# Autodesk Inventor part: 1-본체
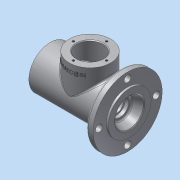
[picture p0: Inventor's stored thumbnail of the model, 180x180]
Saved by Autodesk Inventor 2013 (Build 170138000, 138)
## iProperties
Created: 2016-08
Part Number: 1-본체
Material: 알루미늄 6061
Document SubType Name: Modeling
Designer: Administrator
Density: 2.71 g/cm^3
Mass: 736.795 g
Surface Area: 619.338 cm^2
Volume: 271.88 cm^3
Author: Administrator
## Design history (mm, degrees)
sketch "스케치3"
  geometry: L1 (-57.5, 0)-(57.5, 0); L2 (-28.391, 31)-(57.5, 31); L3 (57.5, 31)-(57.5, 21); L4 (57.5, 21)-(43.5, 16); L5 (43.5, 16)-(43.5, 12.5); L6 (43.5, 12.5)-(38.5, 12.5); L7 (38.5, 12.5)-(38.5, 10); L8 (38.5, 10)-(31.2, 10); L9 (31.2, 10)-(31.2, 16.5); L10 (31.2, 16.5)-(28.5, 16.5); L11 (28.5, 16.5)-(28.5, 17.5); L12 (28.5, 17.5)-(19, 17.5); L13 (19, 17.5)-(19, 26); L14 (19, 26)-(-19, 26); L15 (-19, 26)-(-19, 17.5); L16 (-19, 17.5)-(-31.5, 17.5); L17 (-31.5, 17.5)-(-31.5, 18.5); L18 (-31.5, 18.5)-(-33.25, 18.5); L19 (-33.25, 18.5)-(-33.25, 17.5); L20 (-33.25, 17.5)-(-36.5, 17.5); L21 (-36.5, 17.5)-(-36.5, 20); L22 (-36.5, 20)-(-45.5, 20); L23 (-45.5, 20)-(-45.5, 24); L24 (-45.5, 24)-(-48.5, 24); L25 (-57.5, 12.702)-(-57.5, 31); L26 (-57.5, 31)-(-28.391, 31); L27 (-57.5, 12.702)-(-57.5, 0); L28 (-48.5, 24)-(-48.5, 0); L29 (-48.5, 0)-(-57.5, 0); 3 further points
  constraints: 58 end point, 18 parallel, 6 perpendicular, 3 vertical alignment, 2 horizontal alignment, 2 midpoint, 1 coincident, 1 collinear, 1 horizontal, 1 point on line
  dimensions: "d40" = 42 diameter of L3.end L1; "d43" = 62 diameter of L2 L1; "d44" = 32 diameter of L4.end L1; "d45" = 48 diameter of L24.end L1; "d46" = 40 diameter of L22 L1; "d47" = 35 diameter of L20 L1; "d48" = 37 diameter of L18 L1; "d49" = 25 diameter of L6.end L1; "d50" = 20 diameter of L8 L1; "d51" = 33 diameter of L10 L1; "d52" = 26 distance from line of L16.end L25; "d53" = 12 distance between parallel lines of L23 L25; "d54" = 115 distance of L1.start L1.end; "d55" = 3 distance between parallel lines of L23 L28; "d56" = 21 distance from line of L20.end L25; "d57" = 1.75 distance of L17.end L18.end; "d58" = 14 horizontal distance of L3.end L4.end; "d59" = 5 distance of L5.end L6.end; "d60" = 7.3 distance of L7.end L8.end; "d61" = 2.7 distance of L9.end L10.end; "d62" = 38 distance of L13.end L14.end; "d63" = 52 diameter of L14 L1
revolve "회전1" sketch "스케치3" stored, may be unused: angle "d64" = 90 deg
node "작업 평면1"
sketch "스케치5"
  geometry: C1 r 50 at (0, 0); C2 r 31 at (0, 0) reference; 1 further point
  constraints: 1 centre point, 1 coincident
  dimensions: "d68" = 100 diameter of C1
extrude "돌출3" join sketch "스케치5" distance "d72" = 10; taper "d73" = 0 deg
node "작업 평면2"
sketch "스케치6"
  geometry: C1 r 30 at (0, 0); 1 further point
  constraints: 1 centre point, 1 coincident
  dimensions: "d75" = 60 diameter of C1
extrude "돌출4" join sketch "스케치6" stored distance "d77" = 10; taper "d78" = 0 deg
sketch "스케치7"
  geometry: C1 r 30 at (0, 0) reference; C2 r 19 at (0, 0)
  constraints: 1 centre point, 1 coincident
  dimensions: "d79" = 38 diameter of C2
extrude "돌출5" cut sketch "스케치7" stored distance "d81" = 10; taper "d82" = 0 deg
fillet "모깎기1" dims "d90" = 3
sketch "스케치10"
  geometry: 1 further point
fillet "모깎기3" dims "d92" = 3
chamfer "모따기1" distance "d93" = 1; stored, may be unused: second distance "d94" = 2, angle "d95" = 45 deg
sketch "스케치11" dims "d96" = 83
  geometry: C1 r 31 at (0, 0) reference; C2 r 5 at (0, 41.5); 1 further point
  constraints: 2 vertical alignment, 1 centre point, 1 coincident, 2 other
  dimensions: "d98" = 10 diameter of C2
extrude "돌출6" cut sketch "스케치11" stored distance "d99" = 10; taper "d100" = 0 deg
sketch "스케치13" dims "d104" = 48
  geometry: C1 r 30 at (0, 0) reference; C2 r 20 at (0, 0) reference; 2 further points
  constraints: 2 horizontal alignment, 1 coincident, 2 other
hole "구멍2" sketch "스케치13" at (-24, 0) diameter "d106" = 3.242; stored, may be unused: countersink angle "d110" = 90 deg, drill point angle "d112" = 118 deg; dims "d107" = 8, "d108" = 4, "d109" = 2, "d111" = 10
node "작업 평면3"
sketch "스케치14"
  geometry: L1 (-30, 49)-(30, 49) reference; L2 (-57.5, -31)-(-57.5, 31) reference; 2 further points
  constraints: 1 other
  dimensions: "d117" = 10 distance from line of point (-1.5, 39) L1; "d118" = 56 distance from line of L2 point (-1.5, 39)
feature "엠보싱1" sketch "스케치14" dims "d47" = 35, "d119" = 0.5, "d120" = 0
fillet "모깎기4" dims "d121" = 3
sketch "스케치15"
  geometry: C1 r 31 at (0, 0) reference; 1 further point
  constraints: 1 coincident
hole "구멍3" sketch "스케치15" at (0, 0) diameter "d122" = 37.129; stored, may be unused: countersink angle "d126" = 90 deg, drill point angle "d128" = 118 deg; dims "d123" = 9, "d124" = 4, "d125" = 2, "d127" = 10
fillet "모깎기5" dims "d129" = 3
chamfer "모따기2" distance "d130" = 1; stored, may be unused: second distance "d131" = 2, angle "d132" = 45 deg
fillet "모깎기7" dims "d134" = 2
node "솔리드2"
pattern_circular "원형 패턴1" dims angle "d102" = 360 deg
pattern_circular "원형 패턴2" dims angle "d114" = 360 deg
other parameters: "d67" = -54.5, "d74" = 49
